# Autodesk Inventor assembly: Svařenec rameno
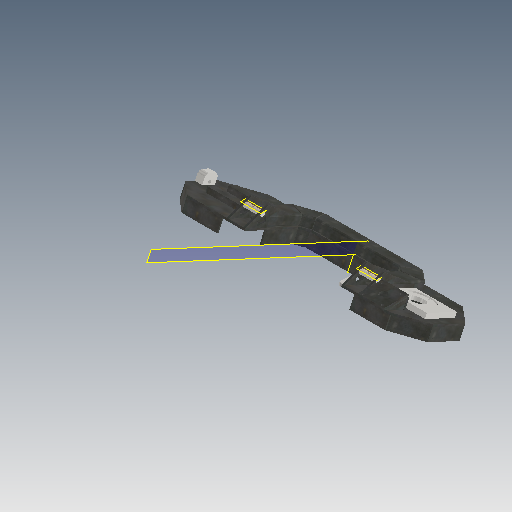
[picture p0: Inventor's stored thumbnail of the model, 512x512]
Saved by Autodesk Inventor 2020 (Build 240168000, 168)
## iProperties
Created: 2025-03
Part Number: Svařenec rameno
Document SubType Name: Assembly
Designer: doma
Mass: 36090.8 g
Surface Area: 14561.2 cm^2
Volume: 4597.55 cm^3
Density: 7.85 g/cm^3
Author: doma
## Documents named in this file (20)
- C:\Users\doma\Desktop\Pásovka záloha\Workgroups\NotInProject\Svařenec rameno.iam
- C:\Users\doma\Desktop\Pásovka záloha\Workgroups\NotInProject\jekl 1.ipt
- C:\Users\doma\Desktop\Pásovka záloha\Workgroups\NotInProject\Plech rameno.ipt
- C:\Users\doma\Desktop\Pásovka záloha\Workgroups\NotInProject\Trojúhelník.ipt
- C:\Users\doma\Desktop\Pásovka záloha\Workgroups\NotInProject\Vedení přední.ipt
- C:\Users\doma\Desktop\Pásovka záloha\Workgroups\NotInProject\Vedení vodítek.ipt
- C:\Users\doma\Desktop\Pásovka záloha\Workgroups\NotInProject\Vedení zadní.ipt
- C:\Users\doma\Desktop\Pásovka záloha\Workgroups\NotInProject\jekl 2.ipt
- C:\Users\doma\Desktop\Pásovka záloha\Workgroups\NotInProject\jekl 3.ipt
- C:\Users\doma\Desktop\Pásovka záloha\Workgroups\NotInProject\Výztuha uchycení čepu.ipt
- C:\Users\doma\Desktop\Pásovka záloha\Workgroups\NotInProject\Deska pod čep.ipt
- C:\Users\doma\Desktop\Pásovka záloha\Workgroups\NotInProject\Pásovina 36.4.ipt
- C:\Users\doma\Desktop\Pásovka záloha\Workgroups\NotInProject\Pásovina 520.ipt
- C:\Users\doma\Desktop\Pásovka záloha\Workgroups\NotInProject\Pásovina 150.ipt
- C:\Users\doma\Desktop\Pásovka záloha\Workgroups\NotInProject\Pásovina 820.ipt
- C:\Users\doma\Desktop\Pásovka záloha\Workgroups\NotInProject\Pásovina 125.8.ipt
- C:\Users\doma\Desktop\Pásovka záloha\Workgroups\NotInProject\Pásovina 154.ipt
- C:\Users\doma\Desktop\Pásovka záloha\Workgroups\NotInProject\Doraz.ipt
- C:\Users\doma\Desktop\Pásovka záloha\Workgroups\NotInProject\Kulatina.ipt
- C:\Users\doma\Desktop\Pásovka záloha\Workgroups\NotInProject\Kostka napínání pásu.ipt
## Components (34 placed, 19 different names)
1. jekl 1:1 — Proti sobě:1, Stejný směr:1, Proti sobě:8, Proti sobě:13, Proti sobě:85
2. Plech rameno:1 — Proti sobě:1, Stejný směr:1, Proti sobě:6, Stejný směr:7, Stejný směr:8, Proti sobě:10, Proti sobě:11, Proti sobě:12, Stejný směr:10, Stejný směr:11, Proti sobě:15, Úhel:1, Proti sobě:20, Proti sobě:22, Proti sobě:23, Proti sobě:25, Proti sobě:26, Proti sobě:29, Stejný směr:23, Proti sobě:42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
3. Vedení přední:1 — Proti sobě:15, Úhel:1, Proti sobě:34, Stejný směr:23
4. Vedení vodítek:1 — Proti sobě:17, Stejný směr:12, Proti sobě:18, Stejný směr:42, Proti sobě:82, Úhel:3
5. Vedení zadní:1 — Proti sobě:22, Proti sobě:23, Proti sobě:24, Proti sobě:33
6. jekl 2:1 — Proti sobě:6, Proti sobě:8, Stejný směr:7, Proti sobě:9
7. jekl 3:1 — Stejný směr:8, Proti sobě:9, Proti sobě:10, Proti sobě:21, Stejný směr:18, Stejný směr:19, Proti sobě:34, Souměrnost:1
8. jekl 2:3 — Proti sobě:11, Proti sobě:13, Proti sobě:14, Stejný směr:10, Proti sobě:85
9. jekl 3:3 — Proti sobě:12, Proti sobě:14, Stejný směr:11, Proti sobě:17, Stejný směr:12, Proti sobě:18, Stejný směr:17, Proti sobě:24, Souměrnost:1
10. Vedení vodítek:2 — Stejný směr:13, Stejný směr:16, Proti sobě:21, Stejný směr:18, Stejný směr:44
11. Vedení vodítek:3 — Stejný směr:13, Stejný směr:14, Stejný směr:15, Stejný směr:16, Stejný směr:19, Proti sobě:81, Úhel:2
12. Vedení vodítek:4 — Stejný směr:14, Stejný směr:15, Proti sobě:20, Stejný směr:17, Proti sobě:28, Stejný směr:43
13. Trojúhelník:1 — Proti sobě:25, Proti sobě:27, Stejný směr:20, Stejný směr:21, Proti sobě:30, Stejný směr:22, Proti sobě:31, Proti sobě:78
14. Trojúhelník:2 — Proti sobě:26, Proti sobě:27, Stejný směr:20, Proti sobě:28
15. Výztuha uchycení čepu:1 — Proti sobě:29, Stejný směr:21, Proti sobě:30, Proti sobě:33
16. Deska pod čep:1 — Stejný směr:22, Proti sobě:31, Proti sobě:78, Stejný směr:47, Proti sobě:84
17. Pásovina 36.4:1 — Proti sobě:44, Stejný směr:26, Proti sobě:48, Proti sobě:63
18. Pásovina 520:1 — Proti sobě:42, Stejný směr:28, Proti sobě:47, Proti sobě:48, Proti sobě:51
19. Pásovina 36.4:2 — Proti sobě:46, Stejný směr:24, Proti sobě:47, Proti sobě:62
20. Pásovina 150:1 — Proti sobě:52, Stejný směr:29, Proti sobě:55, Stejný směr:46
21. Pásovina 150:2 — Proti sobě:53, Stejný směr:30, Proti sobě:54, Proti sobě:70
22. Pásovina 820:1 — Proti sobě:56, Stejný směr:31, Proti sobě:57, Proti sobě:76, Proti sobě:77
23. Pásovina 150:3 — Proti sobě:59, Stejný směr:33, Proti sobě:63
24. Pásovina 150:4 — Proti sobě:60, Stejný směr:35, Proti sobě:62
25. Pásovina 150:5 — Proti sobě:58, Stejný směr:32, Proti sobě:64
26. Pásovina 150:6 — Proti sobě:61, Stejný směr:34, Proti sobě:65, Proti sobě:73
27. Pásovina 125.8:2 — Proti sobě:67, Stejný směr:39, Proti sobě:70
28. Pásovina 125.8:3 — Proti sobě:68, Stejný směr:36, Proti sobě:73
29. Pásovina 154:1 — Proti sobě:74, Stejný směr:41, Proti sobě:76
30. Pásovina 154:2 — Proti sobě:75, Stejný směr:40, Proti sobě:77
31. Doraz:1 — Proti sobě:79, Stejný směr:42, Proti sobě:80
32. Kulatina:1 — Proti sobě:81, Úhel:2, Stejný směr:44
33. Kulatina:2 — Proti sobě:82, Úhel:3, Stejný směr:43
34. Kostka napínání pásu:1 — Proti sobě:83, Stejný směr:45, Stejný směr:46
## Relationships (103: Mate 62, Flush 37, Angle 3, Symmetry 1)
- Proti sobě:1 [Mate]: jekl 1:1 ↔ Plech rameno:1
- Stejný směr:1 [Flush]: jekl 1:1 ↔ Plech rameno:1
- Proti sobě:6 [Mate]: Plech rameno:1 ↔ jekl 2:1
- Proti sobě:8 [Mate]: jekl 1:1 ↔ jekl 2:1
- Stejný směr:7 [Flush]: Plech rameno:1 ↔ jekl 2:1
- Stejný směr:8 [Flush]: Plech rameno:1 ↔ jekl 3:1
- Proti sobě:9 [Mate]: jekl 2:1 ↔ jekl 3:1
- Proti sobě:10 [Mate]: Plech rameno:1 ↔ jekl 3:1
- Proti sobě:11 [Mate]: Plech rameno:1 ↔ jekl 2:3
- Proti sobě:12 [Mate]: Plech rameno:1 ↔ jekl 3:3
- Proti sobě:13 [Mate]: jekl 1:1 ↔ jekl 2:3
- Proti sobě:14 [Mate]: jekl 2:3 ↔ jekl 3:3
- Stejný směr:10 [Flush]: Plech rameno:1 ↔ jekl 2:3
- Stejný směr:11 [Flush]: Plech rameno:1 ↔ jekl 3:3
- Proti sobě:15 [Mate]: Plech rameno:1 ↔ Vedení přední:1
- Úhel:1 [Angle]: Plech rameno:1 ↔ Vedení přední:1
- Proti sobě:17 [Mate]: Vedení vodítek:1 ↔ jekl 3:3
- Stejný směr:12 [Flush]: Vedení vodítek:1 ↔ jekl 3:3
- Proti sobě:18 [Mate]: Vedení vodítek:1 ↔ jekl 3:3
- Stejný směr:13 [Flush]: Vedení vodítek:2 ↔ Vedení vodítek:3
- Stejný směr:14 [Flush]: Vedení vodítek:3 ↔ Vedení vodítek:4
- Stejný směr:15 [Flush]: Vedení vodítek:3 ↔ Vedení vodítek:4
- Stejný směr:16 [Flush]: Vedení vodítek:2 ↔ Vedení vodítek:3
- Proti sobě:20 [Mate]: Plech rameno:1 ↔ Vedení vodítek:4
- Proti sobě:21 [Mate]: jekl 3:1 ↔ Vedení vodítek:2
- Stejný směr:17 [Flush]: jekl 3:3 ↔ Vedení vodítek:4
- Stejný směr:18 [Flush]: jekl 3:1 ↔ Vedení vodítek:2
- Stejný směr:19 [Flush]: jekl 3:1 ↔ Vedení vodítek:3
- Proti sobě:22 [Mate]: Plech rameno:1 ↔ Vedení zadní:1
- Proti sobě:23 [Mate]: Plech rameno:1 ↔ Vedení zadní:1
- Proti sobě:24 [Mate]: Vedení zadní:1 ↔ jekl 3:3
- Proti sobě:25 [Mate]: Plech rameno:1 ↔ Trojúhelník:1
- Proti sobě:26 [Mate]: Plech rameno:1 ↔ Trojúhelník:2
- Proti sobě:27 [Mate]: Trojúhelník:1 ↔ Trojúhelník:2
- Stejný směr:20 [Flush]: Trojúhelník:1 ↔ Trojúhelník:2
- Proti sobě:28 [Mate]: Vedení vodítek:4 ↔ Trojúhelník:2
- Proti sobě:29 [Mate]: Plech rameno:1 ↔ Výztuha uchycení čepu:1
- Stejný směr:21 [Flush]: Trojúhelník:1 ↔ Výztuha uchycení čepu:1
- Proti sobě:30 [Mate]: Trojúhelník:1 ↔ Výztuha uchycení čepu:1
- Stejný směr:22 [Flush]: Trojúhelník:1 ↔ Deska pod čep:1
- Proti sobě:31 [Mate]: Trojúhelník:1 ↔ Deska pod čep:1
- Proti sobě:33 [Mate]: Vedení zadní:1 ↔ Výztuha uchycení čepu:1
- Proti sobě:34 [Mate]: Vedení přední:1 ↔ jekl 3:1
- Stejný směr:23 [Flush]: Plech rameno:1 ↔ Vedení přední:1
- Souměrnost:1 [Symmetry]: jekl 3:1 ↔ jekl 3:3
- Proti sobě:42 [Mate]: Plech rameno:1 ↔ Pásovina 520:1
- Proti sobě:44 [Mate]: Plech rameno:1 ↔ Pásovina 36.4:1
- Proti sobě:46 [Mate]: Plech rameno:1 ↔ Pásovina 36.4:2
- Stejný směr:24 [Flush]: Plech rameno:1 ↔ Pásovina 36.4:2
- Stejný směr:26 [Flush]: Plech rameno:1 ↔ Pásovina 36.4:1
- Stejný směr:28 [Flush]: Plech rameno:1 ↔ Pásovina 520:1
- Proti sobě:47 [Mate]: Pásovina 520:1 ↔ Pásovina 36.4:2
- Proti sobě:48 [Mate]: Pásovina 36.4:1 ↔ Pásovina 520:1
- Proti sobě:51 [Mate]: Pásovina 520:1
- Proti sobě:52 [Mate]: Plech rameno:1 ↔ Pásovina 150:1
- Proti sobě:53 [Mate]: Plech rameno:1 ↔ Pásovina 150:2
- Stejný směr:29 [Flush]: Plech rameno:1 ↔ Pásovina 150:1
- Stejný směr:30 [Flush]: Plech rameno:1 ↔ Pásovina 150:2
- Proti sobě:54 [Mate]: Plech rameno:1 ↔ Pásovina 150:2
- Proti sobě:55 [Mate]: Plech rameno:1 ↔ Pásovina 150:1
- Proti sobě:56 [Mate]: Plech rameno:1 ↔ Pásovina 820:1
- Stejný směr:31 [Flush]: Plech rameno:1 ↔ Pásovina 820:1
- Proti sobě:57 [Mate]: Plech rameno:1 ↔ Pásovina 820:1
- Proti sobě:58 [Mate]: Plech rameno:1 ↔ Pásovina 150:5
- Proti sobě:59 [Mate]: Plech rameno:1 ↔ Pásovina 150:3
- Proti sobě:60 [Mate]: Plech rameno:1 ↔ Pásovina 150:4
- Proti sobě:61 [Mate]: Plech rameno:1 ↔ Pásovina 150:6
- Stejný směr:32 [Flush]: Plech rameno:1 ↔ Pásovina 150:5
- Stejný směr:33 [Flush]: Plech rameno:1 ↔ Pásovina 150:3
- Stejný směr:34 [Flush]: Plech rameno:1 ↔ Pásovina 150:6
- Stejný směr:35 [Flush]: Plech rameno:1 ↔ Pásovina 150:4
- Proti sobě:62 [Mate]: Pásovina 36.4:2 ↔ Pásovina 150:4
- Proti sobě:63 [Mate]: Pásovina 36.4:1 ↔ Pásovina 150:3
- Proti sobě:64 [Mate]: Plech rameno:1 ↔ Pásovina 150:5
- Proti sobě:65 [Mate]: Plech rameno:1 ↔ Pásovina 150:6
- Proti sobě:67 [Mate]: Plech rameno:1 ↔ Pásovina 125.8:2
- Proti sobě:68 [Mate]: Plech rameno:1 ↔ Pásovina 125.8:3
- Stejný směr:36 [Flush]: Plech rameno:1 ↔ Pásovina 125.8:3
- Stejný směr:39 [Flush]: Plech rameno:1 ↔ Pásovina 125.8:2
- Proti sobě:70 [Mate]: Pásovina 150:2 ↔ Pásovina 125.8:2
- Proti sobě:73 [Mate]: Pásovina 150:6 ↔ Pásovina 125.8:3
- Proti sobě:74 [Mate]: Plech rameno:1 ↔ Pásovina 154:1
- Proti sobě:75 [Mate]: Plech rameno:1 ↔ Pásovina 154:2
- Stejný směr:40 [Flush]: Plech rameno:1 ↔ Pásovina 154:2
- Stejný směr:41 [Flush]: Plech rameno:1 ↔ Pásovina 154:1
- Proti sobě:76 [Mate]: Pásovina 820:1 ↔ Pásovina 154:1
- Proti sobě:77 [Mate]: Pásovina 820:1 ↔ Pásovina 154:2
- Proti sobě:78 [Mate]: Trojúhelník:1 ↔ Deska pod čep:1
- Proti sobě:79 [Mate]: Plech rameno:1 ↔ Doraz:1
- Stejný směr:42 [Flush]: Vedení vodítek:1 ↔ Doraz:1
- Proti sobě:80 [Mate]: Plech rameno:1 ↔ Doraz:1
- Proti sobě:81 [Mate]: Vedení vodítek:3 ↔ Kulatina:1
- Proti sobě:82 [Mate]: Vedení vodítek:1 ↔ Kulatina:2
- Úhel:2 [Angle]: Vedení vodítek:3 ↔ Kulatina:1
- Úhel:3 [Angle]: Vedení vodítek:1 ↔ Kulatina:2
- Stejný směr:43 [Flush]: Vedení vodítek:4 ↔ Kulatina:2
- Stejný směr:44 [Flush]: Vedení vodítek:2 ↔ Kulatina:1
- Proti sobě:83 [Mate]: Plech rameno:1 ↔ Kostka napínání pásu:1
- Stejný směr:45 [Flush]: Plech rameno:1 ↔ Kostka napínání pásu:1
- Stejný směr:46 [Flush]: Pásovina 150:1 ↔ Kostka napínání pásu:1
- Stejný směr:47 [Flush]: Deska pod čep:1
- Proti sobě:84 [Mate]: Deska pod čep:1
- Proti sobě:85 [Mate]: jekl 1:1 ↔ jekl 2:3
